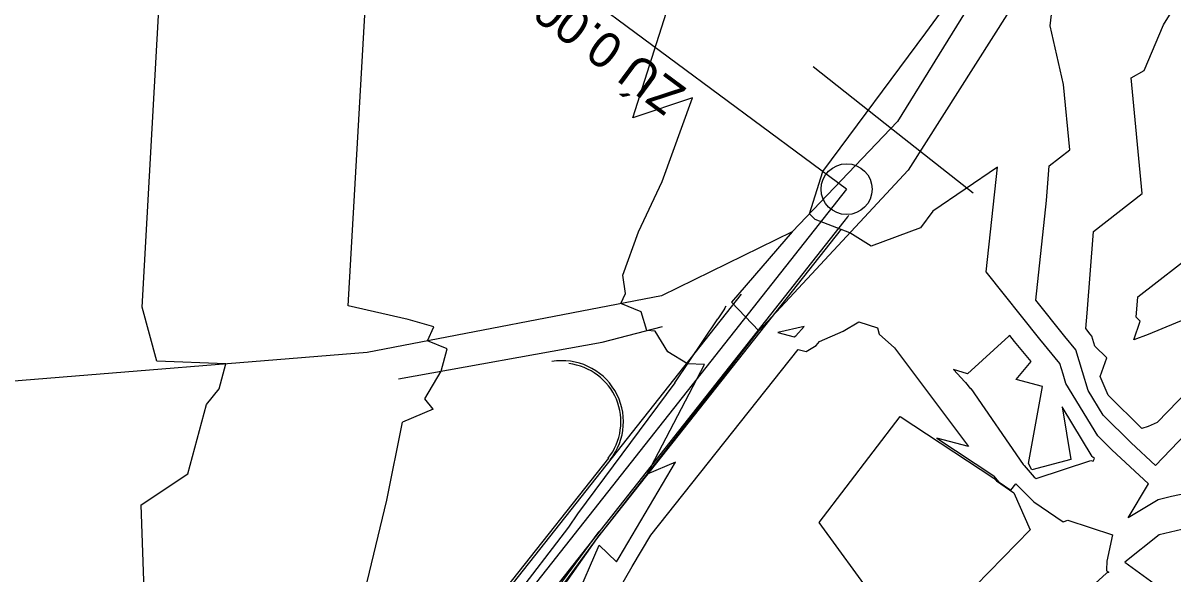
# Model space of a CAD drawing. Extents: x -549394 to -546608, y -1037055 to -1033629.
# Drawn here: x -547740.1 to -547627.3, y -1035433.2 to -1035379.1 of the extents above; entities that cross this region are included whole.
import ezdxf

# ---------------------------------------------------------------- set-up
doc = ezdxf.new("R2010")
doc.units = 0
for name, color, linetype in [('hlavni_vrst', 7, 'Continuous'), ('hrana_L', 7, 'Continuous'), ('norm_vrst', 7, 'Continuous'), ('POLYGONY_SITUACE_PO', 7, 'Continuous'), ('x_navrh_C11', 7, 'Continuous'), ('x_osa_C11', 7, 'Continuous'), ('x_popis_oblouky_C11', 7, 'Continuous'), ('x_popis_pricne_rezy_C11', 7, 'Continuous')]:
    doc.layers.add(name, color=color, linetype=linetype)

msp = doc.modelspace()

# ---------------------------------------------------------------- linework, layer by layer
at = {"layer": 'hlavni_vrst'}
for p, q in [((-547651.52, -1035380.05), (-547650.08, -1035378.1)), ((-547661.62, -1035393.67), (-547651.52, -1035380.05)), ((-547644.51, -1035393.23), (-547650.83, -1035397.56)), ((-547645.62, -1035403.52), (-547644.51, -1035393.23)), ((-547662.95, -1035397.82), (-547661.62, -1035393.67)), ((-547650.83, -1035397.56), (-547652.05, -1035399.2)), ((-547662.37, -1035398.39), (-547662.95, -1035397.82)), ((-547658.97, -1035399.67), (-547662.37, -1035398.39)), ((-547656.9, -1035400.98), (-547658.97, -1035399.67)), ((-547652.05, -1035399.2), (-547656.9, -1035400.98)), ((-547640.35, -1035410.1), (-547645.62, -1035403.52)), ((-547659.65, -1035409.33), (-547658.1, -1035408.42)), ((-547658.1, -1035408.42), (-547656.27, -1035409.01)), ((-547656.27, -1035409.01), (-547656.09, -1035409.61)), ((-547661.95, -1035410.34), (-547659.65, -1035409.33)), ((-547656.09, -1035409.61), (-547654.6, -1035410.95)), ((-547638.38, -1035412.49), (-547640.35, -1035410.1)), ((-547678.52, -1035429.33), (-547664.06, -1035411.12)), ((-547664.06, -1035411.12), (-547663.26, -1035411.34)), ((-547663.26, -1035411.34), (-547662.29, -1035410.73)), ((-547662.29, -1035410.73), (-547661.95, -1035410.34)), ((-547654.6, -1035410.95), (-547647.35, -1035420.64)), ((-547638.06, -1035413.56), (-547638.38, -1035412.49)), ((-547637.78, -1035414.45), (-547638.06, -1035413.56)), ((-547634.65, -1035419.6), (-547637.78, -1035414.45)), ((-547596.99, -1035419.04), (-547627.42, -1035425.56)), ((-547647.35, -1035420.64), (-547650.46, -1035419.84)), ((-547650.46, -1035419.84), (-547644.86, -1035423.52)), ((-547633.26, -1035420.98), (-547634.65, -1035419.6)), ((-547629.69, -1035424.3), (-547633.26, -1035420.98)), ((-547644.33, -1035424.14), (-547644.86, -1035423.52)), ((-547644.33, -1035424.14), (-547643.18, -1035424.92)), ((-547643.18, -1035424.92), (-547642.7, -1035424.3)), ((-547642.7, -1035424.3), (-547640.93, -1035426.07)), ((-547631.68, -1035427.63), (-547629.69, -1035424.3)), ((-547628.73, -1035425.87), (-547631.68, -1035427.63)), ((-547627.42, -1035425.56), (-547628.73, -1035425.87)), ((-547640.93, -1035426.07), (-547638.06, -1035428.05)), ((-547638.06, -1035428.05), (-547637.58, -1035427.89)), ((-547637.58, -1035427.89), (-547635.4, -1035428.6)), ((-547680.35, -1035432.43), (-547678.52, -1035429.33)), ((-547635.4, -1035428.6), (-547633.2, -1035429.31)), ((-547633.2, -1035429.31), (-547633.77, -1035431.89)), ((-547681.72, -1035434.81), (-547680.35, -1035432.43)), ((-547633.77, -1035431.89), (-547633.81, -1035432.76)), ((-547633.81, -1035433.08), (-547635.99, -1035435.06)), ((-547633.81, -1035432.76), (-547633.8, -1035432.83)), ((-547633.58, -1035432.99), (-547633.81, -1035433.08)), ((-547633.8, -1035432.83), (-547633.58, -1035432.99))]:
    msp.add_line(p, q, dxfattribs=at)
at = {"layer": 'hrana_L'}
for p, q in [((-547647.23, -1035377.35), (-547654.32, -1035388.75)), ((-547643.35, -1035377.93), (-547653.27, -1035393.54)), ((-547654.32, -1035388.75), (-547664.64, -1035399.6)), ((-547667.91, -1035409.29), (-547653.27, -1035393.54)), ((-547664.64, -1035399.6), (-547677.46, -1035405.86)), ((-547664.64, -1035399.6), (-547670.59, -1035406.48)), ((-547677.46, -1035405.86), (-547706.33, -1035411.42)), ((-547667.91, -1035409.29), (-547670.59, -1035406.48)), ((-547671.28, -1035407.14), (-547671.94, -1035408.13)), ((-547671.28, -1035407.14), (-547671.11, -1035406.86)), ((-547683.3, -1035410.4), (-547677.37, -1035408.87)), ((-547676.17, -1035414.41), (-547671.94, -1035408.13)), ((-547683.81, -1035429.72), (-547667.91, -1035409.29)), ((-547703.28, -1035414.02), (-547683.3, -1035410.4)), ((-547706.33, -1035411.42), (-547756.77, -1035415.5)), ((-547676.17, -1035414.41), (-547685.69, -1035427.24)), ((-547685.69, -1035427.24), (-547686.59, -1035428.55)), ((-547686.59, -1035428.55), (-547699.54, -1035445.41)), ((-547696.51, -1035447.59), (-547683.81, -1035429.72))]:
    msp.add_line(p, q, dxfattribs=at)
at = {"layer": 'norm_vrst'}
for p, q in [((-547728.43, -1035406.99), (-547724.59, -1035338.68)), ((-547680.29, -1035388.4), (-547668.31, -1035350.8)), ((-547708.21, -1035406.83), (-547705.79, -1035364.36)), ((-547628.21, -1035379.29), (-547619.6, -1035365.22)), ((-547639.31, -1035379.36), (-547638.16, -1035368.73)), ((-547638.01, -1035385.14), (-547639.31, -1035379.36)), ((-547630.09, -1035383.74), (-547628.21, -1035379.29)), ((-547631.37, -1035384.49), (-547630.09, -1035383.74)), ((-547637.41, -1035391.55), (-547638.01, -1035385.14)), ((-547630.31, -1035395.83), (-547631.37, -1035384.49)), ((-547674.41, -1035386.43), (-547680.29, -1035388.4)), ((-547677.41, -1035394.64), (-547674.41, -1035386.43)), ((-547639.43, -1035393.12), (-547637.41, -1035391.55)), ((-547639.68, -1035396.51), (-547639.43, -1035393.12)), ((-547679.71, -1035399.6), (-547677.41, -1035394.64)), ((-547640.73, -1035406.29), (-547639.68, -1035396.51)), ((-547635.08, -1035399.54), (-547630.31, -1035395.83)), ((-547681.26, -1035403.85), (-547679.71, -1035399.6)), ((-547635.68, -1035407.58), (-547635.08, -1035399.54)), ((-547630.73, -1035405.96), (-547623.2, -1035400.1)), ((-547681, -1035405.64), (-547681.26, -1035403.85)), ((-547681.45, -1035406.63), (-547681, -1035405.64)), ((-547679.47, -1035407.42), (-547681.45, -1035406.63)), ((-547637.88, -1035409.86), (-547640.73, -1035406.29)), ((-547630.88, -1035407.97), (-547630.73, -1035405.96)), ((-547620.87, -1035405.97), (-547629.7, -1035409.66)), ((-547726.98, -1035412.27), (-547728.43, -1035406.99)), ((-547702.32, -1035408.17), (-547708.21, -1035406.83)), ((-547678.91, -1035409.27), (-547679.47, -1035407.42)), ((-547635.84, -1035409.07), (-547635.68, -1035407.58)), ((-547699.81, -1035408.9), (-547702.32, -1035408.17)), ((-547700.44, -1035410.29), (-547699.81, -1035408.9)), ((-547663.47, -1035408.86), (-547666.04, -1035409.45)), ((-547664.28, -1035409.78), (-547663.47, -1035408.86)), ((-547631.12, -1035410.18), (-547630.48, -1035408.36)), ((-547630.48, -1035408.36), (-547630.88, -1035407.97)), ((-547678.08, -1035409.33), (-547678.91, -1035409.27)), ((-547676.83, -1035411.37), (-547678.08, -1035409.33)), ((-547666.04, -1035409.45), (-547664.46, -1035409.89)), ((-547664.46, -1035409.89), (-547664.28, -1035409.78)), ((-547643.37, -1035409.82), (-547647.45, -1035413.53)), ((-547643.3, -1035409.74), (-547643.37, -1035409.82)), ((-547642.82, -1035410.34), (-547643.3, -1035409.74)), ((-547636.81, -1035411.15), (-547637.88, -1035409.86)), ((-547635.4, -1035409.61), (-547635.84, -1035409.07)), ((-547635.24, -1035409.81), (-547635.4, -1035409.61)), ((-547634.94, -1035410.81), (-547635.24, -1035409.81)), ((-547629.7, -1035409.66), (-547631.12, -1035410.18)), ((-547698.48, -1035411.07), (-547700.44, -1035410.29)), ((-547699.07, -1035413.26), (-547698.48, -1035411.07)), ((-547641.19, -1035412.32), (-547642.82, -1035410.34)), ((-547636.15, -1035413.32), (-547636.81, -1035411.15)), ((-547633.78, -1035411.94), (-547634.94, -1035410.81)), ((-547720.2, -1035412.54), (-547726.98, -1035412.27)), ((-547674.91, -1035412.54), (-547676.83, -1035411.37)), ((-547642.66, -1035414.07), (-547641.19, -1035412.32)), ((-547634.43, -1035413.79), (-547633.78, -1035411.94)), ((-547622.83, -1035412.07), (-547628.84, -1035418.3)), ((-547720.88, -1035414.99), (-547720.2, -1035412.54)), ((-547700.67, -1035415.98), (-547699.07, -1035413.26)), ((-547678.86, -1035423.36), (-547673.24, -1035412.6)), ((-547673.24, -1035412.6), (-547674.91, -1035412.54)), ((-547647.45, -1035413.53), (-547648.81, -1035413.09)), ((-547648.81, -1035413.09), (-547647.69, -1035414.3)), ((-547635.59, -1035415.14), (-547636.15, -1035413.32)), ((-547647.69, -1035414.3), (-547647.62, -1035414.37)), ((-547647.62, -1035414.37), (-547647.15, -1035415)), ((-547640.08, -1035414.77), (-547642.66, -1035414.07)), ((-547633.62, -1035415.62), (-547634.43, -1035413.79)), ((-547722.1, -1035416.53), (-547720.88, -1035414.99)), ((-547647.15, -1035415), (-547647.11, -1035414.95)), ((-547647.11, -1035414.95), (-547641.97, -1035422.4)), ((-547641.45, -1035422.31), (-547640.08, -1035414.77)), ((-547634.11, -1035417.57), (-547635.59, -1035415.14)), ((-547630.34, -1035418.89), (-547633.62, -1035415.62)), ((-547723.93, -1035423.33), (-547722.1, -1035416.53)), ((-547699.86, -1035417), (-547700.67, -1035415.98)), ((-547635.19, -1035421.62), (-547638.15, -1035416.76)), ((-547638.15, -1035416.76), (-547637.29, -1035421.92)), ((-547699.86, -1035417), (-547702.88, -1035418.25)), ((-547662, -1035428.11), (-547654.04, -1035417.7)), ((-547654.04, -1035417.7), (-547644.84, -1035423.75)), ((-547631.38, -1035420.28), (-547634.11, -1035417.57)), ((-547704.41, -1035425.92), (-547702.88, -1035418.25)), ((-547629.72, -1035418.67), (-547630.34, -1035418.89)), ((-547628.84, -1035418.3), (-547629.72, -1035418.67)), ((-547628.99, -1035422.51), (-547631.38, -1035420.28)), ((-547626, -1035419.41), (-547628.99, -1035422.51)), ((-547681.63, -1035431.55), (-547676.1, -1035422.19)), ((-547676.1, -1035422.19), (-547678.86, -1035423.36)), ((-547641.97, -1035422.4), (-547641.87, -1035422.51)), ((-547641.87, -1035422.51), (-547641.1, -1035423.44)), ((-547641.14, -1035422.95), (-547641.45, -1035422.31)), ((-547637.29, -1035421.92), (-547641.14, -1035422.95)), ((-547640.69, -1035423.79), (-547635.33, -1035422.01)), ((-547635.33, -1035422.01), (-547635.1, -1035422.09)), ((-547635.13, -1035421.68), (-547635.19, -1035421.62)), ((-547634.96, -1035421.84), (-547635.13, -1035421.68)), ((-547635.1, -1035422.09), (-547634.96, -1035421.84)), ((-547728.53, -1035426.36), (-547723.93, -1035423.33)), ((-547641.1, -1035423.44), (-547640.9, -1035423.64)), ((-547640.9, -1035423.64), (-547640.69, -1035423.79)), ((-547644.6, -1035424.03), (-547644.84, -1035423.75)), ((-547644.6, -1035424.03), (-547642.88, -1035425.2)), ((-547707.69, -1035439.57), (-547704.41, -1035425.92)), ((-547642.88, -1035425.2), (-547641.29, -1035428.81)), ((-547727.79, -1035447.08), (-547728.53, -1035426.36)), ((-547653.59, -1035439.61), (-547662, -1035428.11)), ((-547623.62, -1035428.14), (-547628.63, -1035429.3)), ((-547641.29, -1035428.81), (-547651.17, -1035438.94)), ((-547628.63, -1035429.3), (-547632.01, -1035432)), ((-547688.45, -1035441.45), (-547683.57, -1035430.33)), ((-547683.57, -1035430.33), (-547681.88, -1035431.97)), ((-547681.88, -1035431.97), (-547681.63, -1035431.55)), ((-547632.01, -1035432), (-547628.76, -1035434.34))]:
    msp.add_line(p, q, dxfattribs=at)
at = {"layer": 'POLYGONY_SITUACE_PO'}
msp.add_circle((-547659.3, -1035395.4), 2.5, dxfattribs=at)
at = {"layer": 'x_navrh_C11'}
for p, q in [((-547659.57, -1035398.57), (-547689.76, -1035436.82)), ((-547659.84, -1035399.31), (-547683.37, -1035429.12)), ((-547669.65, -1035405.69), (-547692.51, -1035434.65)), ((-547682.68, -1035421.8), (-547692.71, -1035434.49)), ((-547689.5, -1035437.02), (-547683.57, -1035428.97)), ((-547689.3, -1035437.17), (-547683.37, -1035429.12))]:
    msp.add_line(p, q, dxfattribs=at)
for centre, radius, start, end in [((-547541.84, -1035491.52), 150, 141.414, 141.71), ((-547687.2, -1035418.23), 6, 321.71, 99.6966), ((-547687.2, -1035418.23), 5.75, 321.71, 83.5192)]:
    msp.add_arc(centre, radius, start, end, dxfattribs=at)
at = {"layer": 'x_osa_C11'}
msp.add_lwpolyline([(-547659.3, -1035395.4), (-547696.57, -1035442.62)], dxfattribs=at)
at = {"layer": 'x_popis_oblouky_C11'}
msp.add_lwpolyline([(-547659.3, -1035395.4), (-547692.54, -1035370.78)], dxfattribs=at)
at = {"layer": 'x_popis_pricne_rezy_C11'}
msp.add_lwpolyline([(-547646.87, -1035395.8), (-547654.72, -1035389.6), (-547662.57, -1035383.41)], dxfattribs=at)

# ---------------------------------------------------------------- texts
at = {"layer": 'x_popis_oblouky_C11'}
msp.add_text('ZÚ 0.00000', height=3.5, rotation=143.4795, dxfattribs=at).set_placement((-547674.9, -1035385.58))

doc.saveas('drawing.dxf')
